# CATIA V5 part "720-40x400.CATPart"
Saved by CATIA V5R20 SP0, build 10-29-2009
Part number: 720-40x400
Definition: NONE
Nomenclature: 720-40x400
Source: Unknown
Description: 720-40x400
Bounding box of the stored display mesh (mm): x 0 to 400, y -20 to 20, z -20 to 20
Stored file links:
  C:\Users\Utente\Desktop\IO LAVORO\3D X SITO CF\X SITO\720\720-40x400.CATPart

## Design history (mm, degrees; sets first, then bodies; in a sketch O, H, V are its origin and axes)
Body1 "720-40x400" (main body)
  Solid1: solid without history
